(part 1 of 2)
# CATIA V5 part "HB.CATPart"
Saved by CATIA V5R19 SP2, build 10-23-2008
Part number: Part5
Material "Aluminium Grey": density 7860 kg/m3, Young's modulus 2e+11 Pa, Poisson ratio 0.266
Bounding box of the stored display mesh (mm): x -1447 to 1983, y -709.728 to 766.546, z 0 to 764.137
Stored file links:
  C:\BEHROOZ\catia learning\tarh haye mashin\hb\HB.CATPart
  C:\catia\intel_a\startup\materials\Catalog.CATMaterial
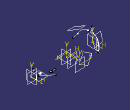
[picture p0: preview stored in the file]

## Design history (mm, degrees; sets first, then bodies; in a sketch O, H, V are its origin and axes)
Set1 "body"
  Plane1: type 3Points, Element1 Point172, Element2 Point171, Element3 vertex of DatumCurve110
  Point1: (0, 560, 0), relative to DatumPoint1
  DatumPoint1
  Point2: (0, 543, 0), relative to DatumPoint2
  DatumPoint2
  Point3: (0, 590, 0), relative to DatumPoint3
  DatumPoint3
  Sketch1, origin (0, 0, 0), H (-1, 0, 0), V (0, 0, 1), geometry linked from another document
  DatumCurve1 to DatumCurve32
  Line1: type PtPt, FirstPoint Point171, SecondPoint vertex of Project2
  Line2: type PtPt, FirstPoint Point171, SecondPoint Point172
  Line3: type PtPt, FirstPoint Point1, SecondPoint Point2
  Point4: (0, 650, -9), relative to vertex of DatumCurve6
  Point5: (102, 660, 41), relative to vertex of DatumCurve5
  Line4: type PtPt, FirstPoint Point2, SecondPoint Point4
  Line5: type PtPt, FirstPoint Point3, SecondPoint Point5
  Line6: type PtPt, FirstPoint Point5, SecondPoint Point4
  MultiSel1
  Project1: ToProject DatumCurve110, Support Plane10
  Line7: type PtPt, FirstPoint Point172, SecondPoint vertex of Project1
  Point6: (0, 650, 0), relative to vertex of DatumCurve3
  Plane2: type 3Points, Element1 Point3, Element2 Point6, Element3 Point171
  Sketch2 on Plane2, origin (-78.0124, 775.8037, 117.3869), H (0.9943, 0.1069, 0.001), V (0.0149, -0.1487, 0.9888)
    arc A1 centre (-572.2266, 197.2665) radius 593.2723 from (-1107.0923, 453.9584) to (-1139.7624, 24.4222) ccw
    point P3 (-1139.7624, 24.4222)
  Line8: type PtPt, FirstPoint Sketch2.P3, SecondPoint vertex of MultiSel1
  Sketch3 on Plane10, origin (0, 750, 0), H (-1, 0, 0), V (0, 0, 1)
    point P3 (-1376.9419, 458.1904)
    construction arc A1 centre (-1402.6201, 208.1688) radius 251.3368 from (-1151.2833, 208.1688) to (-1653.9569, 208.1688) ccw
    arc A2 centre (-1402.6201, 208.1688) radius 251.3368 from (-1376.9419, 458.1904) to (-1542.2672, 417.1398) ccw
  Project2: ToProject DatumCurve114, Support Plane10
  Line9: type PtPt, FirstPoint Point1, SecondPoint Sketch3.P3
  Point7: (0, 450, 0), relative to vertex of DatumCurve14
  Point8: (0, 500, 0), relative to vertex of DatumCurve27
  Line10: type PtPt, FirstPoint Point1, SecondPoint Point7
  Point9: (0, 550, 0), relative to vertex of DatumCurve31
  Line11: type PtPt, FirstPoint Point9, SecondPoint Point8
  Point10: (0, 673, 0), relative to vertex of DatumCurve29
  Point11: (0, 645, 0), relative to vertex of DatumCurve28
  Point12: (0, 539, 0), relative to vertex of DatumCurve27
  Line12: type PtPt, FirstPoint Point9, SecondPoint Point10
  Line13: type PtPt, FirstPoint Point10, SecondPoint Point11
  Point13: (0, 618, 0), relative to vertex of DatumCurve16
  Point14: (0, 507, 0), relative to vertex of DatumCurve15
  Plane3: type 3Points, Element1 Point11, Element2 Point12, Element3 Point9
  Plane4: type 3Points, Element1 Point13, Element2 Point14, Element3 Point9
  Sketch4 on Plane3, origin (5.635, 663.249, 505.9147), H (0.9996, 0.0229, 0.0148), V (-0.0073, -0.2968, 0.9549)
    arc A1 centre (-594.4461, -2004.0603) radius 2784.6452 from (1168.2244, 151.6858) to (681.189, 471.2182) ccw
  Sketch5 on Plane4, origin (-9.0268, 746.4765, 250.6891), H (0.9999, 0.0121, 0), V (0.0038, -0.3183, 0.948)
    arc A1 centre (-726.5939, -2122.185) radius 3228.8457 from (1224.9549, 450.1489) to (691.4704, 778.5974) ccw
  Plane5: type 3Points, Element1 Point8, Element2 Point12, Element3 Point10
  Plane6: type 3Points, Element1 Point7, Element2 Point14, Element3 Point10
  Sketch6 on Plane5, origin (-37.1347, 730.2999, 224.4996), H (-0.9987, -0.0508, 0), V (0.0149, -0.2931, 0.956)
    arc A1 centre (-734.4471, -9769.1716) radius 10544.7974 from (431.1665, 711.0047) to (-709.6236, 775.5965) ccw
  Sketch7 on Plane6, origin (-43.1111, 726.7872, 263.5719), H (-0.9982, -0.0592, 0), V (0.0202, -0.3398, 0.9403)
    arc A1 centre (-608.5163, -13864.5538) radius 14636.2047 from (477.9525, 731.2701) to (-714.2086, 771.2694) ccw
  Point15: (0, 464, 0), relative to vertex of DatumCurve17
  Plane7: type 3Points, Element1 Point13, Element2 Point15, Element3 vertex of DatumCurve17
  Sketch8 on Plane7, origin (469.0299, 0, 1021.215), H (0, -1, 0), V (-0.9087, 0, 0.4174)
    arc A1 centre (1554.2833, -625.2206) radius 2181.3334 from (-618, -823.7165) to (-507, -1338.8918) ccw
    arc A2 centre (-331.1603, -1278.0114) radius 186.0806 from (-507, -1338.8918) to (-387.6065, -1455.3242) ccw
    arc A3 centre (44.2123, -98.8631) radius 1423.5358 from (-387.6065, -1455.3242) to (-2.1616, -1521.6434) ccw
    point P7 (-2.1616, -1521.6434)
  Point16: type OnCurve, Support Line9, Length 2237.11
  Line14: type PtPt, FirstPoint Point16, SecondPoint Point13
  Line15: type PtPt, FirstPoint Point8, SecondPoint Point7
  Line16: type PtPt, FirstPoint Point11, SecondPoint Point13
  Corner1: Element1 Sketch5, Element2 Sketch7, Radius 150, Direction (0, 0, 1)
  Corner2: Element1 Sketch4, Element2 Sketch6, Radius 150, Direction (0, 0, 1)
  MultiSel2
  Point17: type OnCurve, Support DatumCurve17, Length 94.325
  Point18: (-83, 601, 34), relative to Point17
  Symmetry1: ToTransfor Point18, Reference zx-plane
  Point19: (83, 0, 0), relative to vertex of DatumCurve15
  Point20: (-70, 493, 0), relative to Point19
  Symmetry2: ToTransfor Point20, Reference zx-plane
  Point21: type OnCurve, Support Corner1, Length 272.021
  Point22: (6, -19, 0), relative to Point21
  Curve1: Elements (Point20; Point22; Point18)
  DatumCurve33 to DatumCurve39
  Corner3: Element1 DatumCurve37, Element2 DatumCurve38, Radius 21, Direction (0, 0, 1)
  Fill1: Boundary (DatumCurve33; DatumCurve39; Corner3; DatumCurve36; DatumCurve35; DatumCurve34)
  Point23: (-77, 0, 6), relative to vertex of DatumCurve14
  Point24: (37, 0, 12), relative to vertex of DatumCurve15
  Curve2: Elements (Point7; Point23; vertex of MultiSel2)
  Point25: type OnCurve, Support Corner1, Length 631.686
  Symmetry3: ToTransfor Point25, Reference zx-plane
  Curve3: Elements (Point25; Point24; Symmetry3)
  Point26: type OnCurve, Support DatumCurve15, Length 651.239
  Point27: (0, 0, 6), relative to Point26
  Project3: ToProject Point26, Support {symmetry ToTransfor Corner1, Reference zx-plane}
  Project4: ToProject Point26, Support Corner1
  Curve4: Elements (Project4; Point27; Project3)
  Curve5: Elements (vertex of DatumCurve34; Point18; Point13)
  Curve6: Elements (vertex of DatumCurve35; Symmetry1; vertex of MultiSel2)
  Line17: type PtPt, FirstPoint vertex of MultiSel2, SecondPoint Sketch8.P7
  Point28: type OnCurve, Support Sketch8, Length 882.114
  Point29: (-274, 218, 159), relative to Point28
  Point30: type OnCurve, Support DatumCurve35, Length -20
  Curve7: Elements (Point28; Point29; Point30)
  Symmetry4: ToTransfor Curve7, Reference zx-plane
  Symmetry5: ToTransfor Curve1, Reference zx-plane
  Corner4: Element1 Curve7, Element2 Curve1, Radius 66, Direction (0, 0, 1)
  Corner5: Element1 Symmetry4, Element2 Symmetry5, Radius 66, Direction (0, 0, 1)
  Point31: (-274, 110, 143), relative to Point28
  Point32: type OnCurve, Support DatumCurve35, Length 197.392
  Curve8: Elements (Point28; Point31; Point32)
  Symmetry6: ToTransfor Curve8, Reference zx-plane
  Fill2: Boundary (Curve8; DatumCurve35; Symmetry6; {symmetry ToTransfor Sketch8, Reference zx-plane}; Line17; Sketch8)
  Fill3: Boundary ({fillboundary BoundaryWire Curve8, Support Fill2}; DatumCurve35; DatumCurve34; Corner4)
  Symmetry7: ToTransfor Fill3, Reference zx-plane
  Corner6: Element1 Sketch8, Element2 Corner1, Radius 150, Direction (0, 0, 1)
  Corner7: Element1 {symmetry ToTransfor Sketch8, Reference zx-plane}, Element2 {symmetry ToTransfor Corner1, Reference zx-plane}, Radius 150, Direction (0, 0, 1)
  Point33: (8, -10, -1), relative to vertex [face of Corner6 | element of Sketch5]
  Curve9: Elements (vertex [face of Corner6 | element of Sketch5]; Point33; vertex [face of Curve1 | face of Corner4])
  Fill4: Boundary (Corner6; Corner4; Curve9)
  Symmetry8: ToTransfor Fill4, Reference zx-plane
  Point34: type OnCurve, Support Corner6, Length 2289.743
  Point35: (-24, 24, -8), relative to Point34
  Line18: type PtPt, FirstPoint Point34, SecondPoint Point35
  Point36: type OnCurve, Support Corner6, Length 2584.885
  Point37: type OnCurve, Support Corner6, Length 2064.27
  Point38: (-24, 32, -8), relative to Point37
  Curve10: Elements (Point11; Point38; Point35)
  Corner8: Element1 Corner2, Element2 Curve10, Radius 150, Direction (0, 0, 1)
  Point39: (31, -10, 4), relative to vertex [element of Sketch4 | face of Corner8]
  Curve11: Elements (vertex [element of Sketch4 | face of Corner8]; Point39; vertex [face of Corner6 | element of Sketch5])
  Point40: (-21, -22, 24), relative to Point8
  Fill5: Boundary (Line18; Corner8; Curve11; Corner6)
  Symmetry9: ToTransfor Fill5, Reference zx-plane
  Point41: (0, -17, 14), relative to vertex [element of Sketch6 | face of Corner2]
  Curve12: Elements (vertex [element of Sketch6 | face of Corner2]; Point41; vertex [face of Corner1 | element of Sketch7])
  Fill6: Boundary (Corner8; {fillboundary BoundaryWire Curve11, Support Fill5}; Corner6; Curve12)
  Symmetry10: ToTransfor Fill6, Reference zx-plane
  Corner9: Element1 Line11, Element2 Corner8, Radius 150, Direction (0, 0, 1)
  Corner10: Element1 Corner6, Element2 Line10, Radius 2000, Direction (0, 0, 1)
  Corner11: Element1 {symmetry ToTransfor Corner2, Reference zx-plane}, Element2 {symmetry ToTransfor Line11, Reference zx-plane}, Radius 150, Direction (0, 0, 1)
  Corner12: Element1 Corner7, Element2 {symmetry ToTransfor Line10, Reference zx-plane}, Radius 150, Direction (0, 0, 1)
  Corner13: Element1 Line13, Element2 Line12, Radius 150, Direction (0, 0, 1)
  Corner14: Element1 Corner9, Element2 Corner13, Radius 10, Direction (0, 0, 1)
  DatumCurve40 to DatumCurve50
  Corner15: Element1 DatumCurve40, Element2 DatumCurve49, Radius 18, Direction (0, 0, 1)
  Point42: (-26, 65, -168), relative to Point41
  Point43: type OnCurve, Support DatumCurve42, Length 1090.97
  Curve13: Elements (Point43; Point42; vertex [element of Sketch4 | face of Corner2])
  Fill7: Boundary (DatumCurve42; Curve13; DatumCurve48; Corner15; DatumCurve41)
  Fill8: Boundary (DatumCurve42; DatumCurve43; DatumCurve44; DatumCurve45; DatumCurve46; DatumCurve47; {fillboundary BoundaryWire Curve13, Support Fill7})
  Join1: Elements (Fill7; Fill8)
  Symmetry11: ToTransfor Join1, Reference zx-plane
  Point44: (0, -47, 18), relative to Project4
  Point45: (0, -25, 6), relative to Project4
  Point46: type OnCurve, Support Corner10, Length 905.12
  Point47: (0, -40, 17), relative to Point46
  Point48: (0, -72, 33), relative to Point46
  Point49: (-24, -4, 7), relative to Point20
  Point50: (-9, -2, 3), relative to Point20
  Curve14: Elements (Point49; Point50; vertex of DatumCurve33)
  Curve15: Elements (Point49; Point44; Point48)
  Corner16: Element1 Curve14, Element2 Curve15, Radius 124, Direction (0, 0, 1)
  Curve16: Elements (Project4; Point45; Point44)
  Point51: (-24, -9, 5), relative to Point25
  Point52: type OnCurve, Support Corner16, Length 976.244
  Curve17: Elements (vertex of Curve12; Point51; Point52)
  Point53: (0, -9, 1), relative to Point21
  Curve18: Elements (Point21; Point53; Point22)
  Fill9: Boundary (Curve18; Corner4; {fillboundary BoundaryWire Curve9, Support Fill4}; Corner10)
  Point54: (0, -9, 3), relative to vertex [element of Sketch5 | face of Corner1]
  Curve19: Elements (vertex [element of Sketch5 | face of Corner1]; Point54; vertex of DatumCurve33)
  Fill10: Boundary (Curve19; Corner10; {fillboundary BoundaryWire Curve18, Support Fill9}; Corner4)
  Fill11: Boundary ({fillboundary BoundaryWire Curve19, Support Fill10}; Corner16; Curve17; Corner10)
  Join2: Elements (Fill9; Fill10; Fill11)
  Symmetry12: ToTransfor Join2, Reference zx-plane
  Fill12: Boundary ({fillboundary BoundaryWire Curve17, Support Join2}; Corner16; Curve16; Corner10)
  Symmetry13: ToTransfor Fill12, Reference zx-plane
  Point55: (0, -127, 20), relative to Point48
  Point56: (0, -198, 11), relative to Point44
  Point57: (0, -288, 0), relative to Point52
  Line19: type PtPt, FirstPoint Point48, SecondPoint Point55
  Curve20: Elements (Point55; Point56; Point57)
  Point58: (20, -198, 0), relative to Point57
  MultiSel3
  Curve21: Elements (Point57; Point58; vertex of MultiSel3)
  Corner17: Element1 Curve21, Element2 Curve20, Radius 124, Direction (0, 0, 1)
  Corner18: Element1 Corner17, Element2 {symmetry ToTransfor Curve20, Reference zx-plane}, Radius 124, Direction (0, 0, 1)
  Point59: (0, -11, -14), relative to Point44
  Point60: (10, -30, -21), relative to Point48
  Point61: (8, 14, -37), relative to Point55
  Point62: (0, 20, -17), relative to Point56
  Point63: (0, 22, -4), relative to vertex [face of Corner17 | face of Curve20]
  Curve22: Elements (Point52; Point59; Point60)
  Line20: type PtPt, FirstPoint Point60, SecondPoint Point61
  Curve23: Elements (Point61; Point62; Point63)
  Point64: (49, -56, -2), relative to Point57
  Point65: (36, 0, -9), relative to Point24
  Point66: type OnCurve, Support Corner18, Ratio 0.5
  Point67: type OnCurve, Support Corner3, Ratio 0.5
  DatumCurve51 to DatumCurve53
  Point68: type OnCurve, Support DatumCurve51, Ratio 0.5
  Point69: (64, 0, -3), relative to Point66
  Curve24: Elements (Point66; Point69; Point65; Point68)
  Curve25: Elements (Point63; Point57; Point64; Point69)
  Symmetry14: ToTransfor Curve25, Reference zx-plane
  Point70: (0, -12, 1), relative to Point63
  Curve26: Elements (Point63; Point70; vertex [face of Corner17 | face of Curve20])
  Fill13: Boundary (Curve25; Curve24; Corner18; Curve26)
  Corner19: Element1 Corner18, Element2 Line19, Radius 26, Direction (0, 0, 1)
  Corner20: Element1 Corner16, Element2 Corner19, Radius 26, Direction (0, 0, 1)
  Corner21: Element1 Curve23, Element2 Line20, Radius 26, Direction (0, 0, 1)
  Corner22: Element1 Corner21, Element2 Curve22, Radius 26, Direction (0, 0, 1)
  Line21: type PtPt, FirstPoint vertex [face of Curve23 | face of Corner21], SecondPoint vertex [face of Corner19 | face of Curve20]
  Line22: type PtPt, FirstPoint vertex [face of Corner22 | face of Curve22], SecondPoint vertex [face of Curve15 | face of Corner20]
  Fill14: Boundary ({fillboundary BoundaryWire Curve26, Support Fill13}; Corner20; Line21; Corner22)
  Fill15: Boundary (Corner22; Line22; Corner20; {fillboundary BoundaryWire Line21, Support Fill14})
  Fill16: Boundary ({fillboundary BoundaryWire Line22, Support Fill15}; Corner22; Corner20)
  Join3: Elements (Fill16; Fill15; Fill14; Fill13)
  Symmetry15: ToTransfor Join3, Reference zx-plane
  Point71: (0, 106, 0), relative to Point63
  Point72: type OnCurve, Support Corner22, Ratio 0.04
  Curve27: Elements (Point72; Point71; Point63)
  Fill17: Boundary (Corner22; Curve27)
  DatumCurve54 to DatumCurve69
  Point73: (0, -12, 0), relative to Point52
  Split1: ToCut DatumCurve65, Cutting Point72
  Curve28: Elements (Point72; Point73; vertex of DatumCurve39)
  Fill18: Boundary (Curve28; {fillboundary BoundaryWire Curve27, Support Fill17}; Curve25; Curve24; DatumCurve51)
  Fill19: Boundary (DatumCurve39; {fillboundary BoundaryWire Curve28, Support Fill18}; Split1; DatumCurve63; DatumCurve64)
  Join4: Elements (Fill18; Fill19; Fill17)
  Symmetry16: ToTransfor Join4, Reference zx-plane
  Point74: (-103, 0, 0), relative to vertex of DatumCurve1
  Curve29: Elements (vertex of MultiSel2; Point74; Point1)
  Point75: (-103, 0, -43), relative to vertex of DatumCurve1
  Symmetry17: ToTransfor Point2, Reference zx-plane
  Curve30: Elements (Symmetry17; Point75; Point2)
  Line23: type PtPt, FirstPoint Point75, SecondPoint Point74
  Corner23: Element1 Line9, Element2 Curve29, Radius 270, Direction (0, 0, 1)
  Corner24: Element1 Line4, Element2 Curve30, Radius 270, Direction (0, 0, 1)
  Symmetry18: ToTransfor Point3, Reference zx-plane
  Point76: (-103, 0, 71), relative to vertex of DatumCurve4
  Curve31: Elements (Point3; Point76; Symmetry18)
  Line24: type PtPt, FirstPoint Point75, SecondPoint Point76
  Corner25: Element1 Line5, Element2 Curve31, Radius 270, Direction (0, 0, 1)
  Point77: (-52, 0, -41), relative to Point76
  Line25: type PtPt, FirstPoint Point76, SecondPoint Point77
  Point78: (-75, 0, -72), relative to vertex [face of Corner25 | face of Curve31]
  Point79: type OnCurve, Support Sketch2, Ratio 0.53
  Point80: (-23, -76, 0), relative to Point79
  Point81: type OnCurve, Support Corner25, Ratio 0.42
  Point82: (-64, 0, -43), relative to Point81
  Curve32: Elements (Point77; Point82; Point78; Point80; Point6)
  Corner26: Element1 Line8, Element2 Curve32, Radius 270, Direction (0, 0, 1)
  Corner27: Element1 {project ToProject DatumCurve109, Support Plane10}, Element2 {project ToProject DatumCurve108, Support Plane10}, Radius 100, Direction (0, 0, 1)
  Corner28: Element1 {project ToProject DatumCurve107, Support Plane10}, Element2 Corner26, Radius 27, Direction (0, 0, 1)
  Corner29: Element1 Line7, Element2 Line2, Radius 132, Direction (0, 0, 1)
  Corner30: Element1 Corner29, Element2 Line1, Radius 33, Direction (0, 0, 1)
  Point83: (33, -14, -33), relative to vertex [face of Line9 | face of Corner23]
  Curve33: Elements (vertex [face of Line9 | face of Corner23]; Point83; vertex [face of Line4 | face of Corner24])
  Point84: (-140, 68, -300), relative to vertex [face of Line5 | face of Corner25]
  Curve34: Elements (vertex [face of MultiSel1 | face of Corner28]; Point84; vertex [face of Line5 | face of Corner25])
  Fill20: Boundary (Curve34; Corner25; Line6; Corner24; Curve33; Corner23; Project2; Corner30; Project1; Corner27; Corner28)
  DatumCurve70 to DatumCurve75
  Line26: type PtPt, FirstPoint vertex [face of Corner23 | face of Curve29], SecondPoint vertex [face of Corner24 | face of Curve30]
  Fill21: Boundary (Line26; DatumCurve74; {fillboundary BoundaryWire edge of Fill20, Support Fill20}; DatumCurve71)
  Fill22: Boundary (DatumCurve70; {fillboundary BoundaryWire Line26, Support Fill21}; DatumCurve73; Line23)
  Point85: (60, -14, -33), relative to Point79
  Curve35: Elements (Point80; Point85; Point84)
  Fill23: Boundary ({fillboundary BoundaryWire edge of Fill20, Support Fill20}; Corner28; Curve35)
  Fill24: Boundary ({fillboundary BoundaryWire edge of Fill20, Support Fill20}; Corner25; Line25; Corner28; {fillboundary BoundaryWire edge of Fill23, Support Fill23})
  Point86: type OnCurve, Support DatumCurve72, Ratio 0.67
  Point87: type OnCurve, Support Corner25, Ratio 0.7
  Line27: type PtPt, FirstPoint Point87, SecondPoint Point86
  Fill25: Boundary (Line27; DatumCurve72; {fillboundary BoundaryWire edge of Fill20, Support Fill20}; Corner25)
  Join5: Elements (Fill20; Fill25; Fill21; Fill22; Fill24; Fill23)
  Symmetry19: ToTransfor Join5, Reference zx-plane
  Point88: type OnCurve, Support Corner10, Ratio 0.24
  Point89: (-644, -100, -78), relative to Point88
  Symmetry20: ToTransfor Point89, Reference zx-plane
  Point90: (0, 0, 50), relative to vertex of DatumCurve1
  Curve36: Elements (Symmetry20; Point90; Point89)
  Curve37: Elements (Point89; Point88)
  Corner31: Element1 Curve36, Element2 Curve37, Radius 165, Direction (0, 0, 1)
  Line28: type PtPt, FirstPoint Point74, SecondPoint Point90
  Point91: type OnCurve, Support DatumCurve74, Ratio 0.47
  Curve38: Elements (Point88; Point91)
  Curve39: Elements (vertex [face of Line9 | face of Corner23]; vertex [face of Corner14 | face of Line12])
  Fill26: Boundary ({fillboundary BoundaryWire Curve12, Support Fill6}; Corner10; Curve38; DatumCurve74; Curve39; DatumCurve43; DatumCurve44; DatumCurve45; DatumCurve46)
  Fill27: Boundary ({fillboundary BoundaryWire Curve38, Support Fill26}; DatumCurve74; DatumCurve73; Line28; Corner31)
  Join6: Elements (Fill27; Fill26)
  Symmetry21: ToTransfor Join6, Reference zx-plane
  Point92: (-19, -34, -6), relative to vertex [face of Curve21 | face of Corner18]
  Point93: (0, 19, -6), relative to vertex [face of Corner18 | face of MultiSel3]
  Point94: type OnCurve, Support DatumCurve54, Ratio 0.56
  Point95: (0, 18, -9), relative to Point94
  Point96: (0, 58, -36), relative to vertex of MultiSel3
  Point97: (-400, 28, -72), relative to Point96
  Curve40: Elements (Point93; Point95; Point96; Point97)
  Point98: (0, 0, -5), relative to Point66
  Curve41: Elements (Point98; Point92; Point93)
  Corner32: Element1 Curve41, Element2 Curve40, Radius 165, Direction (0, 0, 1)
  Point99: (-500, -60, -200), relative to Point23
  Curve42: Elements (Point99; Point97)
  MultiSel4
  Corner33: Element1 Corner32, Element2 {symmetry ToTransfor Corner32, Reference zx-plane}, Radius 143, Direction (0, 0, 1)
  Curve43: Elements (Point88; Point47; vertex [face of Corner20 | face of Line19])
  Fill28: Boundary (Curve43; DatumCurve61; DatumCurve62; {fillboundary BoundaryWire Curve16, Support Fill12}; edge of Fill26; edge of Fill26)
  Symmetry22: ToTransfor Fill28, Reference zx-plane
  Point100: (-7, -188, 17), relative to Point47
  Point101: type OnCurve, Support Symmetry23, Ratio 0.16
  Curve44: Elements (Point101; Point100; vertex [face of Line19 | face of Corner19])
  Point102: type OnCurve, Support Corner33, Ratio 0.5
  Point103: type OnCurve, Support DatumCurve56, Ratio 0.5
  Line29: type PtPt, FirstPoint Point102, SecondPoint Point103
  Point104: type OnCurve, Support DatumCurve57, Ratio 0.54
  Point105: type OnCurve, Support Corner33, Ratio 0.44
  Curve45: Elements (Point96; Point95; vertex of DatumCurve54)
  Symmetry23: ToTransfor Curve45, Reference zx-plane
  DatumCurve76 to DatumCurve82
  Curve46: Elements (Point101; vertex of MultiSel4)
  Point106: (0, -90, 22), relative to vertex [face of Fill27]
  Curve47: Elements (vertex of MultiSel4; Point106; vertex [face of Fill27])
  Point107: type OnCurve, Support DatumCurve60, Ratio 0.5
  Point108: (400, 0, 93), relative to Point106
  Curve48: Elements (Point106; Point108; Point107)
  Corner34: Element1 Curve42, Element2 {symmetry ToTransfor Curve42, Reference zx-plane}, Radius 84, Direction (0, 0, 1)
  Curve49: Elements (Point88; vertex of DatumCurve70)
  Point109: type OnCurve, Support DatumCurve70, Ratio 0.5
  Point110: type OnCurve, Support Corner34, Ratio 0.5
  Point111: (-42, 0, -34), relative to Point110
  Curve50: Elements (Point75; Point111; Point110)
  Point112: type OnCurve, Support Curve46, Ratio 0.33
  Curve51: Elements (Point112; Point100; vertex of DatumCurve60)
  Split2: ToCut Symmetry23, Cutting Point101
  Fill29: Boundary (Curve46; Split2; edge of Fill14; edge of Fill15; Curve51)
  Corner35: Element1 Corner34, Element2 Curve46, Radius 800, Direction (0, 0, 1)
  Fill30: Boundary ({fillboundary BoundaryWire Curve51, Support Fill29}; DatumCurve60; {fillboundary BoundaryWire edge of Fill28, Support Fill28}; Curve49; DatumCurve70; Curve50; Corner35)
  MultiSel5
  Plane8: type Offset, RefPlane yz-plane, Offset -1447
  Sketch9 on Plane8, origin (-1447, 0, 0), H (0, 1, 0), V (0, 0, 1)
    arc A1 centre (164.0273, 530.3883) radius 252.5722 from (361.0039, 688.4798) to (359.7121, 690.076) ccw
    arc A2 centre (78.6045, -7421.7668) radius 8188.4956 from (0, 766.3516) to (203.3096, 765.7792) cw
    arc A3 centre (200.1736, 559.8853) radius 205.9178 from (203.3096, 765.7792) to (359.7121, 690.076) cw
    arc A4 centre (-164.0273, 530.3883) radius 252.5722 from (-361.0039, 688.4798) to (-359.7121, 690.076) cw
    arc A5 centre (-78.6045, -7421.7668) radius 8188.4956 from (0, 766.3516) to (-203.3096, 765.7792) ccw
    arc A6 centre (-200.1736, 559.8853) radius 205.9178 from (-203.3096, 765.7792) to (-359.7121, 690.076) ccw
  Join7: Elements (Symmetry19; Join5)
  Project5: ToProject Sketch9, Support Join7, Direction DatumCurve13
  Split3: ToCut Join7, Cutting Project5
  Point113: (-86, 0, -73), relative to vertex [face of Symmetry21]
  Curve52: Elements (vertex [face of Symmetry21]; Point113; vertex of Project5)
  Fill31: Boundary (Curve52; edge of MultiSel5; edge of Symmetry21; edge of Symmetry21)
  Symmetry24: ToTransfor Fill31, Reference zx-plane
  Point114: (-38, 0, -22), relative to Point90
  Curve53: Elements (vertex [face of Project5 | face of Project5]; Point114; Point90)
  Fill32: Boundary ({fillboundary BoundaryWire edge of Fill31, Support Fill31}; edge of Symmetry21; Curve53; Project5)
  Symmetry25: ToTransfor Fill32, Reference zx-plane
  Fill33: Boundary (edge of MultiSel5; edge of MultiSel5; edge of MultiSel5; DatumCurve55; DatumCurve56; DatumCurve57; Split2; edge of Fill29; edge of Fill30; edge of Fill30; edge of Fill30; edge of Fill30; edge of MultiSel5; edge of MultiSel5; edge of MultiSel5)
  MultiSel6
  DatumCurve83
  Point115: (0, -31, 0), relative to vertex [face of Corner30 | face of Line1]
  Point116: (0, -31, 0), relative to vertex [face of Corner30 | face of Line2]
  Point117: (0, -31, 0), relative to vertex [face of Line2 | face of Corner29]
  Point118: (0, -31, 0), relative to vertex [face of Corner29 | face of Line7]
  Line30: type PtPt, FirstPoint Point117, SecondPoint Point116, Start 89, End 84
  Curve54: Elements (Point118; vertex of Project1)
  Curve55: Elements (Point115; vertex of Project2)
  Corner36: Element1 Curve55, Element2 Line30, Radius 33, Direction (0, 0, 1)
  Corner37: Element1 Corner36, Element2 Curve54, Radius 133, Direction (0, 0, 1)
  Split4: ToCut {project ToProject DatumCurve24, Support Plane10, Direction DatumCurve83}, Cutting Corner37
  Fill34: Boundary (Corner37; Split4; {project ToProject DatumCurve23, Support Plane10, Direction DatumCurve83})
  Line31: type PtPt, FirstPoint Point118, SecondPoint vertex [face of Line7 | face of Corner29]
  Line32: type PtPt, FirstPoint Point115, SecondPoint vertex [face of Corner30 | face of Line1]
  Line33: type PtPt, FirstPoint Point116, SecondPoint vertex [face of Line2 | face of Corner30]
  Line34: type PtPt, FirstPoint Point117, SecondPoint vertex [face of Line2 | face of Corner29]
  DatumCurve84 to DatumCurve93
  Fill35: Boundary (Line33; DatumCurve92; Line32; DatumCurve85)
  Fill36: Boundary (Line34; DatumCurve86; {fillboundary BoundaryWire Line33}; DatumCurve91; DatumCurve90)
  Fill37: Boundary ({fillboundary BoundaryWire Line34, Support Fill36}; DatumCurve90; Line31; DatumCurve87)
  Fill38: Boundary ({fillboundary BoundaryWire Line31, Support Fill37}; DatumCurve90; DatumCurve89; DatumCurve88)
  Fill39: Boundary ({fillboundary BoundaryWire Line32, Support Fill35}; DatumCurve92; DatumCurve93; DatumCurve84)
  MultiSel7
  Project6: ToProject DatumCurve24, Support Plane10, Direction DatumCurve94
  DatumCurve94
  Point119: (0, 94, -55), relative to Point28
  Point120: type OnCurve, Support {project ToProject DatumCurve23, Support Plane10, Direction DatumCurve83}, Ratio 0.64
  Point121: (210, -165, -67), relative to Point120
  Point122: type OnCurve, Support edge of Fill4, Ratio 0.72
  Point123: (26, 0, -81), relative to Point122
  Curve56: Elements (Point120; Point121; Point123; Point119)
  Point124: type OnCurve, Support Curve56, RefPoint Point123, Ratio -1.58
  Point125: type OnCurve, Support DatumCurve50, Ratio 0.64
  Point126: (160, 26, -127), relative to Point125
  Curve57: Elements (Point125; Point126; Point124)
  Corner38: Element1 Curve57, Element2 Curve56, Radius 133, Direction (0, 0, 1)
  Split5: ToCut Curve57, Cutting Point126
  Fill40: Boundary (Corner38; Split5; {fillboundary BoundaryWire DatumCurve50}; {fillboundary BoundaryWire edge of Fill5}; edge of Fill7; edge of Fill7; DatumCurve41; edge of Fill7; edge of Fill8; {fillboundary BoundaryWire Curve39, Support Join6}; DatumCurve75; {project ToProject DatumCurve23, Support Plane10, Direction DatumCurve83}; Curve56)
  Point127: (109, 2, -79), relative to Point35
  Point128: (77, 26, -55), relative to Point35
  Point129: (-10, 0, 27), relative to Point123
  Symmetry26: ToTransfor Corner10, Reference zx-plane
  Extrapol1: ToExtrapol edge of Fill5, Support Fill5, Length 34
  Extrapol2: ToExtrapol edge of Symmetry9, Support Symmetry9, Length 34
  DatumCurve95 to DatumCurve98
  Join8: Elements edge of Extrapol1
  Corner39: Element1 Join8, Element2 Line18, Radius 80, Direction (0, 0, 1)
  Join9: Elements edge of Fill5
  Corner40: Element1 Corner39, Element2 edge of Fill5, Radius 80, Direction (0, 0, 1)
  Sketch10 on Plane10, origin (0, 750, 0), H (-1, 0, 0), V (0, 0, 1)
    frozenspline C1
    arc A1 centre (-1623.9406, 563.3388) radius 83.2719 from (-1625.9642, 480.0915) to (-1588.3124, 488.0737) ccw
  Project7: ToProject Sketch10, Support Extrapol1, Direction edge of Sketch11
  Sketch11, origin (0, 0, 0), H (1, 0, 0), V (0, 1, 0), geometry linked from another document
  Symmetry27: ToTransfor Project7, Reference zx-plane
  Split6: ToCut Extrapol1, Cutting Project7
  Split7: ToCut Extrapol2, Cutting Symmetry27
  Symmetry28: ToTransfor Fill40, Reference zx-plane
  Point130: (-10, 17, 20), relative to Point119
  Point131: type OnCurve, Support DatumCurve97, Ratio 0.27
  Point132: (5, 4, -28), relative to Point131
  Curve58: Elements (vertex of Project7; Point128; Point127; Point129; Point130)
  Point133: (5, 4, -21), relative to Point122
  Point134: (5, 4, -20), relative to Point36
  Curve59: Elements (vertex of Project7; Point132; Point133; Point134)
  Point135: type OnCurve, Support DatumCurve98, Ratio 0.38
  Curve60: Elements (Point119; Point28)
  Curve61: Elements (Point130; Point135)
  Corner41: Element1 Curve60, Element2 Curve56, Radius 96, Direction (0, 0, 1)
  Corner42: Element1 Curve61, Element2 Curve58, Radius 95, Direction (0, 0, 1)
  Point136: type OnCurve, Support {project ToProject DatumCurve23, Support Plane10, Direction DatumCurve83}, Ratio 0.77
  Point137: type OnCurve, Support Project6, Ratio 0.31
  Point138: (53, -87, -79), relative to Point119
  Point139: type OnCurve, Support DatumCurve12, Ratio 0.18
  Point140: (42, 0, 18), relative to Point139
  Symmetry29: ToTransfor Point138, Reference zx-plane
  Point141: type OnCurve, Support Corner41, Ratio 0.62
  Curve62: Elements (Symmetry29; Point140; Point138)
  Curve63: Elements (Point138; Point141)
  DatumCurve99
  Symmetry30: ToTransfor Curve63, Reference zx-plane
  Corner43: Element1 Curve62, Element2 Curve63, Radius 95, Direction (0, 0, 1)
  Corner44: Element1 Symmetry30, Element2 Corner43, Radius 95, Direction (0, 0, 1)
  Point142: (42, 0, -54), relative to Point124
  Point143: (73, -70, -104), relative to Point123
  Point144: (37, 0, -103), relative to Point138
  Curve64: Elements (Point136; Point142; Point143; Point144)
  Point145: (-15, 100, -54), relative to Point144
  Point146: (-43, 179, -85), relative to Point144
  Curve65: Elements (Point144; Point145; Point146)
  Corner45: Element1 Curve65, Element2 Curve64, Radius 91, Direction (0, 0, 1)
  Point147: (39, -35, -276), relative to Point142
  Point148: type OnCurve, Support Project6, Ratio 0.26
  Curve66: Elements (Point148; Point147; Point146)
  Point149: (-39, 37, -42), relative to Point147
  Point150: (-7, 0, -52), relative to Point146
  Point151: (10, -38, -47), relative to Point145
  Point152: (9, 0, -44), relative to Point144
  Point153: (0, 0, -44)
  Point154: (0, 0, -44)
  Curve67: Elements (Point137; Point149; Point150; Point151; Point152)
  Point155: (35, 0, -121), relative to Point140
  Symmetry31: ToTransfor Point152, Reference zx-plane
  Curve68: Elements (Point152; Point155; Symmetry31)
  Symmetry32: ToTransfor Curve67, Reference zx-plane
  Point156: (18, 0, -31), relative to Point140
  Corner46: Element1 Curve68, Element2 Curve67, Radius 105, Direction (0, 0, 1)
  Corner47: Element1 Symmetry32, Element2 Corner46, Radius 105, Direction (0, 0, 1)
  Point157: (22, 0, -31), relative to vertex [face of Curve62 | face of Corner43]
  Point158: (37, 0, -111), relative to vertex [face of Curve62 | face of Corner43]
  Curve69: Elements (vertex [face of Curve62 | face of Corner43]; Point157; Point158; vertex [face of Corner46 | face of Curve68])
  Symmetry33: ToTransfor Curve69, Reference zx-plane
  Fill41: Boundary (Curve69; Corner44; Symmetry33; Corner47)
  Fill42: Boundary ({fillboundary BoundaryWire Curve69, Support Fill41}; Corner47; Project6; Curve66; Corner45; {project ToProject DatumCurve23, Support Plane10, Direction DatumCurve83}; Corner41; Corner44)
  Symmetry34: ToTransfor Fill42, Reference zx-plane
  Point159: (-9, 0, -105), relative to Point155
  Point160: (-20, 0, -100), relative to vertex [face of Corner46 | face of Curve68]
  Point161: (-5, 0, -21), relative to vertex [face of Corner46 | face of Curve67]
  Point162: (-5, 0, 22), relative to Point146
  Point163: (5, 0, 53), relative to Point147
  Curve70: Elements (Point165; Point163; Point162; Point161; Point160)
  Point164: type OnCurve, Support Curve66, Ratio 0.24
  Point165: (-5, 0, 67), relative to Point164
  Point166: (20, -15, 128), relative to Point165
  Point167: (-11, 0, 141), relative to Point163
  Point168: (-33, -18, 166), relative to Point162
  Point169: (-69, 0, 267), relative to Point161
  Point170: (-37, 0, 303), relative to Point159
  Symmetry35: ToTransfor Point169, Reference zx-plane
  Curve71: Elements (Point169; Point170; Symmetry35)
  Curve72: Elements (Point166; Point167; Point168; Point169)
  Symmetry36: ToTransfor Point160, Reference zx-plane
  Curve73: Elements (Point160; Point159; Symmetry36)
  Corner48: Element1 Curve73, Element2 Curve70, Radius 105, Direction (0, 0, 1)
  Corner49: Element1 Curve72, Element2 Curve71, Radius 66, Direction (0, 0, 1)
  Plane9: type OffsetPt, RefPlane zx-plane, RefPoint Point159
  Sketch12 on Plane9, origin (0, 0, 0), H (-1, 0, 0), V (0, 0, 1)
    line L1 (-1873.4872, 3.0401) -> (-1872.0391, 15.2461)
    line L2 (-1872.0391, 15.2461) -> (-1938.0896, 21.6317)
    arc A1 centre (-1866.8797, 159.6994) radius 156.7986 from (-1873.4872, 3.0401) to (-1938.505, 20.216) cw
    arc A2 centre (-1938.1619, 20.8841) radius 0.7511 from (-1938.505, 20.216) to (-1938.0896, 21.6317) cw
